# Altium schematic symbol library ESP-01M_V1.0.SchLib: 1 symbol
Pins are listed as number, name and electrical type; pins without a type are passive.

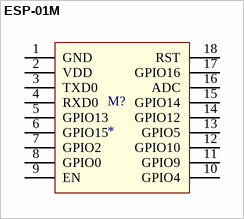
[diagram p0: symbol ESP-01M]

## ESP-01M
designator M?
footprint ESP-01M
pins: 1 GND, 2 VDD, 3 TXD0, 4 RXD0, 5 GPIO13, 6 GPIO15, 7 GPIO2, 8 GPIO0, 9 EN, 10 GPIO4, 11 GPIO9, 12 GPIO10, 13 GPIO5, 14 GPIO12, 15 GPIO14, 16 ADC, 17 GPIO16, 18 RST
